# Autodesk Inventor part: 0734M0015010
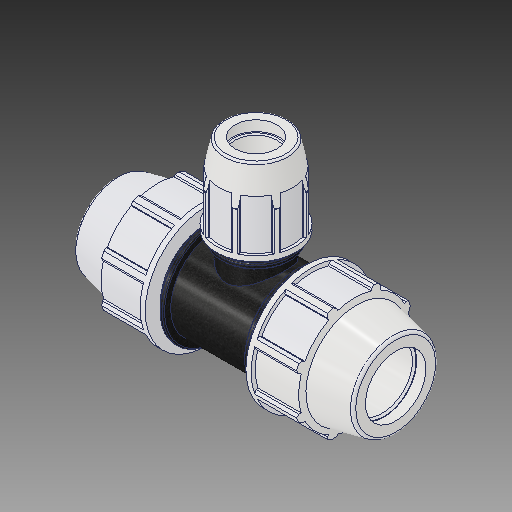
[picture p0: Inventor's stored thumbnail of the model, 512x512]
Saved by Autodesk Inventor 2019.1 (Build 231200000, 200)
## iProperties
Created: 2017-02
Part Number: 0734M0015010
Material: PVC-Piping
Description: PLASSON REDUCING TEE 1 1/2'' - 1'' - 1 1/2''
Document SubType Name: Modeling
Designer: KIM
Mass: 92.6774 g
Surface Area: 199.44 cm^2
Volume: 66.1981 cm^3
Density: 1.4 g/cm^3
Appearance: PTFE
Author: Кирилл
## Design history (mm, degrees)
derived "0734M0.ipt"
feature "Solid1::0734M0.ipt"
feature "Solid2::0734M0.ipt"
tag "TaggingFeature1"
body "Solid1"
other parameters: "d2" = 48.1, "d4" = 9.24983, "d5" = 31.07944, "d7" = 96.012, "d11" = 3.69993, "d13" = 120 deg, "d14" = 67.34, "d15" = 12 deg, "d16" = 83.53044, "d18" = 2.405, "d19" = 35 deg, "d20" = 17.5 deg, "d21" = 89.29116, "d23" = 0, "d25" = 360 deg, "d27" = 1.92024, "d33" = 0.962, "d42" = 39.95928, "d43" = 2.88036, "d46" = 1.443, "d67" = 72.009, "d76" = 33.3, "d77" = 62.992, "d78" = 12 deg, "d79" = 116.078, "d80" = 120 deg, "d81" = 49.95, "d82" = 9.67317, "d87" = 3.86927, "d89" = 29.0195, "d90" = 34.8234, "d96" = 18.49967, "d98" = 58.58256, "d99" = 35 deg, "d100" = 17.5 deg, "d102" = 0, "d103" = 1.25984, "d107" = 360 deg, "d109" = 0.999, "d112" = 1.665, "d113" = 4.19947, "d114" = 0, "d117" = 221.996, "d118" = 54.80304, "d126" = 43.29, "d127" = 92.964, "d131" = 4.64312, "d132" = 29.97, "d133" = 66.04, "d135" = 0, "d138" = 4.43992, "d143" = 0, "d148" = 47.244, "d168" = 43.29, "d170" = 0, "d171" = 33.3, "d173" = 0, "d176" = 4.19947, "d177" = 0, "d_" = 48.1, "E_" = 96.012, "A_" = 116.078, "l_" = 92.964, "E_1" = 62.992, "l_1" = 66.04, "d_1" = 33.3, "H_" = 221.996
